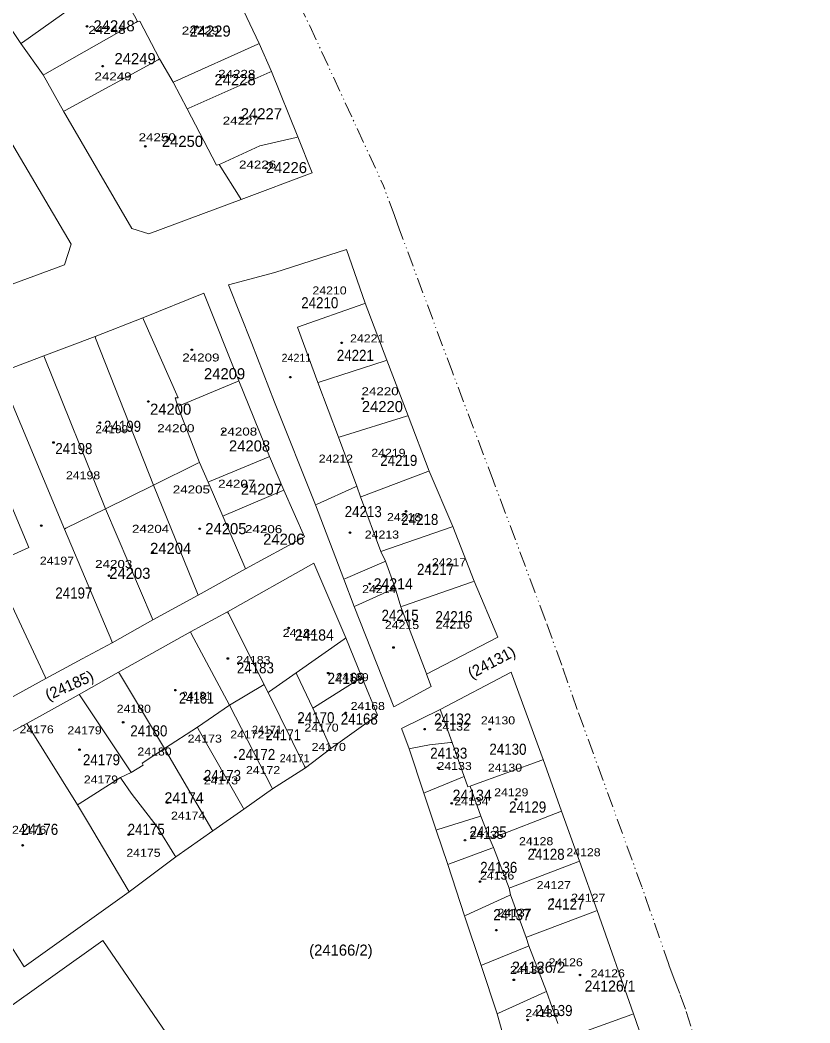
# Model space of a CAD drawing. Extents: x 649608 to 651081, y 237980 to 241202.
# Drawn here: x 650824.6 to 651081.3, y 238660.5 to 238986.3 of the extents above; entities that cross this region are included whole.
import ezdxf

# ---------------------------------------------------------------- set-up
doc = ezdxf.new("R2010")
doc.units = 0
doc.header["$PDMODE"] = 32
doc.header["$PDSIZE"] = 0.5
doc.linetypes.add('DASH_DOUBLE_DOT', pattern=[9.2, 5, -1.2, 0.3, -1.2, 0.3, -1.2])
for name, color, linetype in [('19', 7, 'Continuous'), ('20', 7, 'Continuous'), ('6', 7, 'Continuous')]:
    doc.layers.add(name, color=color, linetype=linetype)
for name, color, linetype, lineweight in [('3', 7, 'Continuous', 13), ('5', 7, 'Continuous', 13), ('52', 7, 'DASH_DOUBLE_DOT', 13)]:
    doc.layers.add(name, color=color, linetype=linetype, lineweight=lineweight)

msp = doc.modelspace()

# ---------------------------------------------------------------- linework, layer by layer
at = {"layer": '3'}
for p, q in [((650919.551, 238936.638), (650896.474, 238928.024)), ((650893.931, 238625.308), (650851.505, 238687.244))]:
    msp.add_line(p, q, dxfattribs=at)
for points in [[(650896.474, 238928.024), (650866.501, 238916.902), (650860.911, 238918.598), (650838.751, 238956.69), (650832.15, 238968.489), (650824.903, 238978.716), (650815.286, 238992.747), (650804.439, 239005.498)], [(650919.551, 238936.638), (650914.867, 238948.335), (650906.317, 238969.569), (650902.354, 238978.677), (650891.135, 239002.272)], [(650820.054, 238949.367), (650841.243, 238913.534), (650838.995, 238906.77), (650799.963, 238892.432), (650770.275, 238881.011), (650758.748, 238876.78), (650749.256, 238873.381), (650736.765, 238868.633), (650722.035, 238862.95)], [(650892.348, 238900.274), (650907.377, 238904.347), (650930.698, 238911.753), (650936.802, 238894.323), (650943.788, 238875.768), (650950.717, 238857.717), (650957.619, 238839.792), (650965.263, 238821.75), (650972.163, 238804.001), (650979.843, 238785.835)], [(650892.348, 238900.274), (650899.901, 238881.247), (650907.252, 238862.117), (650920.617, 238828.809), (650929.839, 238804.682), (650933.238, 238795.794), (650946.119, 238763.137)], [(650895.76, 238869.115), (650884.379, 238897.633), (650864.531, 238889.545), (650848.962, 238883.51), (650832.372, 238877.214), (650817.719, 238871.717), (650805.539, 238866.947), (650792.518, 238861.842), (650760.407, 238849.915)], [(650897.827, 238808.065), (650917.045, 238818.418), (650910.287, 238833.538), (650905.707, 238844.466), (650895.76, 238869.115)], [(650758.169, 238660.693), (650714.231, 238692.51), (650714.379, 238696.621), (650773.885, 238729.057), (650787.528, 238736.436), (650826.802, 238757.704), (650843.776, 238767.23), (650856.602, 238774.451), (650879.964, 238787.538), (650892.055, 238793.996), (650920.073, 238809.821)], [(650920.073, 238809.821), (650930.477, 238785.555), (650935.71, 238772.766)], [(650833.004, 238772.406), (650844.737, 238778.761), (650854.588, 238784.015), (650867.719, 238791.491), (650882.507, 238799.486), (650897.827, 238808.065)], [(650946.119, 238763.137), (650958.223, 238769.746), (650956.746, 238773.738), (650979.843, 238785.835)], [(650791.939, 238782.111), (650803.989, 238756.472), (650833.004, 238772.406)], [(650948.594, 238756.104), (650961.145, 238762.316), (650984.226, 238774.453)], [(650984.226, 238774.453), (650984.338, 238774.16), (650994.654, 238746.036), (651000.56, 238729.25)], [(650935.71, 238772.766), (650940.785, 238760.481), (650925.609, 238749.684), (650917.325, 238743.359), (650906.695, 238736.485), (650897.365, 238729.873), (650887.272, 238722.827), (650875.247, 238714.403), (650860.075, 238703.102)], [(650948.594, 238756.104), (650948.647, 238755.953), (650951.021, 238749.525), (650955.792, 238735.14), (650959.886, 238723.149), (650963.669, 238711.97), (650969.049, 238695.287), (650974.422, 238679.159), (650979.638, 238663.433), (650982.757, 238652.196), (650986.731, 238637.816), (650991.239, 238621.324), (650995.965, 238603.801), (650998.364, 238595.203), (651001.152, 238574.45)], [(651063.379, 238461.895), (651063.305, 238462.395), (651061.473, 238474.842), (651059.17, 238490.663), (651056.406, 238508.519), (651054.341, 238525.331), (651052.076, 238542.318), (651049.059, 238560.151), (651043.67, 238600.336), (651038.659, 238621.53), (651031.567, 238641.552), (651023.953, 238663.427), (651012.132, 238696.964), (651006.434, 238713.032), (651000.56, 238729.25)], [(650860.075, 238703.102), (650825.962, 238678.677), (650821.773, 238685.221)], [(650851.505, 238687.244), (650818.255, 238663.558), (650782.391, 238637.529), (650824.601, 238580.584), (650833.018, 238586.179), (650832.688, 238586.745), (650893.931, 238625.308)]]:
    msp.add_lwpolyline(points, dxfattribs=at)
at = {"layer": '5'}
for points in [[(650824.903, 238978.716), (650825.403, 238979.072), (650854.809, 239000.028), (650861.825, 238987.705), (650862.766, 238985.824)], [(650832.15, 238968.489), (650832.65, 238968.772), (650862.266, 238985.541), (650862.766, 238985.824)], [(650862.766, 238985.824), (650863.556, 238986.011), (650869.959, 238973.705), (650874.391, 238966.117), (650878.962, 238957.522)], [(650874.391, 238966.117), (650874.891, 238966.342), (650901.854, 238978.452), (650902.354, 238978.677)], [(650838.751, 238956.69), (650839.251, 238956.963), (650869.459, 238973.432), (650869.959, 238973.705)], [(650878.962, 238957.522), (650879.462, 238957.742), (650905.817, 238969.349), (650906.317, 238969.569)], [(650878.962, 238957.522), (650888.424, 238939.149), (650889.341, 238939.413)], [(650889.341, 238939.413), (650889.841, 238939.641), (650902.508, 238945.405), (650914.367, 238948.216), (650914.867, 238948.335)], [(650889.341, 238939.413), (650896.161, 238928.524), (650896.474, 238928.024)], [(650914.737, 238886.554), (650936.302, 238894.147), (650936.802, 238894.323)], [(650864.531, 238889.545), (650864.751, 238889.045), (650875.984, 238863.567), (650874.962, 238863.579), (650875.863, 238860.74), (650882.87, 238842.564), (650885.704, 238836.141), (650890.457, 238825.101)], [(650941.848, 238813.662), (650935.229, 238831.363), (650934.09, 238834.906), (650928.106, 238850.774), (650921.359, 238868.55), (650914.737, 238886.554)], [(650848.962, 238883.51), (650849.159, 238883.01), (650867.955, 238835.238)], [(650832.372, 238877.214), (650832.573, 238876.714), (650852.38, 238827.525)], [(650921.359, 238868.55), (650921.859, 238868.711), (650943.288, 238875.607), (650943.788, 238875.768)], [(650817.719, 238871.717), (650817.929, 238871.217), (650839.016, 238820.925)], [(650875.863, 238860.74), (650876.363, 238860.95), (650895.26, 238868.905), (650895.76, 238869.115)], [(650827.458, 238814.978), (650805.75, 238866.447), (650805.539, 238866.947)], [(650928.106, 238850.774), (650928.606, 238850.928), (650950.217, 238857.563), (650950.717, 238857.717)], [(650867.955, 238835.238), (650882.37, 238842.318), (650882.87, 238842.564)], [(650885.704, 238836.141), (650886.204, 238836.349), (650905.207, 238844.258), (650905.707, 238844.466)], [(650935.229, 238831.363), (650935.729, 238831.551), (650957.119, 238839.604), (650957.619, 238839.792)], [(650839.016, 238820.925), (650839.516, 238821.172), (650852.38, 238827.525), (650867.955, 238835.238)], [(650867.955, 238835.238), (650882.303, 238799.986), (650882.507, 238799.486)], [(650890.457, 238825.101), (650890.957, 238825.314), (650909.787, 238833.325), (650910.287, 238833.538)], [(650934.09, 238834.906), (650933.59, 238834.68), (650921.117, 238829.035), (650920.617, 238828.809)], [(650852.38, 238827.525), (650867.506, 238791.991), (650867.719, 238791.491)], [(650890.457, 238825.101), (650897.611, 238808.565), (650897.827, 238808.065)], [(650839.016, 238820.925), (650854.377, 238784.515), (650854.588, 238784.015)], [(650965.263, 238821.75), (650964.763, 238821.577), (650941.848, 238813.662)], [(650816.298, 238809.995), (650816.798, 238810.218), (650827.458, 238814.978)], [(650941.848, 238813.662), (650943.392, 238810.452), (650946.482, 238801.788), (650948.392, 238795.682)], [(650943.392, 238810.452), (650942.892, 238810.239), (650930.339, 238804.895), (650929.839, 238804.682)], [(650972.163, 238804.001), (650971.663, 238803.826), (650948.892, 238795.857), (650948.392, 238795.682)], [(650946.482, 238801.788), (650945.982, 238801.562), (650933.738, 238796.02), (650933.238, 238795.794)], [(650821.271, 238797.545), (650832.771, 238772.906), (650833.004, 238772.406)], [(650903.916, 238770.428), (650892.307, 238793.496), (650892.055, 238793.996)], [(650948.392, 238795.682), (650956.556, 238774.238), (650956.746, 238773.738)], [(650879.964, 238787.538), (650880.231, 238787.038), (650892.673, 238763.728)], [(650914.297, 238774.216), (650929.977, 238785.205), (650930.477, 238785.555)], [(650856.602, 238774.451), (650856.902, 238773.951), (650871.499, 238749.614)], [(650905.198, 238767.795), (650905.698, 238768.148), (650914.297, 238774.216)], [(650914.297, 238774.216), (650914.536, 238773.716), (650919.796, 238762.706)], [(650860.71, 238741.886), (650864.617, 238744.264), (650864.265, 238744.852), (650871.499, 238749.614), (650882.228, 238756.559), (650892.673, 238763.728), (650903.916, 238770.428)], [(650903.916, 238770.428), (650904.159, 238769.928), (650905.198, 238767.795)], [(650919.796, 238762.706), (650920.296, 238763.022), (650935.21, 238772.45), (650935.71, 238772.766)], [(650860.71, 238741.886), (650860.376, 238742.386), (650844.11, 238766.73), (650843.776, 238767.23)], [(650905.198, 238767.795), (650917.077, 238743.859), (650917.325, 238743.359)], [(650892.673, 238763.728), (650906.438, 238736.985), (650906.695, 238736.485)], [(650919.796, 238762.706), (650925.386, 238750.184), (650925.609, 238749.684)], [(650961.145, 238762.316), (650961.327, 238761.816), (650965.051, 238751.593), (650968.909, 238740.542)], [(650843.322, 238731.299), (650827.115, 238757.204), (650826.802, 238757.704)], [(650897.365, 238729.873), (650897.081, 238730.373), (650882.512, 238756.059), (650882.228, 238756.559)], [(650951.021, 238749.525), (650951.521, 238749.626), (650957.675, 238750.87), (650964.551, 238751.544), (650965.051, 238751.593)], [(650871.499, 238749.614), (650886.978, 238723.327), (650887.272, 238722.827)], [(650970.888, 238737.388), (650971.388, 238737.57), (650994.154, 238745.854), (650994.654, 238746.036)], [(650843.322, 238731.299), (650843.822, 238731.618), (650857.248, 238740.177), (650860.71, 238741.886)], [(650857.248, 238740.177), (650857.595, 238739.677), (650860.756, 238735.125), (650869.187, 238724.182), (650874.937, 238714.903), (650875.247, 238714.403)], [(650955.792, 238735.14), (650956.292, 238735.346), (650968.409, 238740.336), (650968.909, 238740.542)], [(650968.909, 238740.542), (650970.097, 238737.227), (650970.888, 238737.388), (650974.373, 238727.694), (650977.245, 238720.162), (650978.452, 238717.453), (650983.561, 238704.298), (650984.021, 238702.059), (650989.061, 238688.248), (650989.987, 238685.484), (650995.652, 238670.697), (650999.401, 238660.225)], [(650860.075, 238703.102), (650859.779, 238703.602), (650846.865, 238725.39), (650843.322, 238731.299)], [(650959.886, 238723.149), (650960.386, 238723.306), (650973.873, 238727.537), (650974.373, 238727.694)], [(650977.245, 238720.162), (650977.745, 238720.357), (651000.56, 238729.25)], [(650963.669, 238711.97), (650964.169, 238712.155), (650977.952, 238717.268), (650978.452, 238717.453)], [(650983.561, 238704.298), (650984.061, 238704.489), (651005.934, 238712.841), (651006.434, 238713.032)], [(650969.049, 238695.287), (650969.549, 238695.513), (650983.521, 238701.833), (650984.021, 238702.059)], [(650989.061, 238688.248), (650989.561, 238688.437), (651011.632, 238696.775), (651012.132, 238696.964)], [(650974.422, 238679.159), (650974.922, 238679.362), (650989.487, 238685.281), (650989.987, 238685.484)], [(650979.638, 238663.433), (650980.138, 238663.66), (650995.152, 238670.47), (650995.652, 238670.697)], [(651000.938, 238655.114), (651023.453, 238663.246), (651023.953, 238663.427)]]:
    msp.add_lwpolyline(points, dxfattribs=at)
at = {"layer": '52'}
for points in [[(650586.911, 239277.281), (650736.548, 239179.048), (650838.83, 239107.702), (650862.891, 239089.627), (650874.137, 239074.489), (650882.719, 239057.758), (650918.743, 238984.453), (650942.749, 238932.427)], [(651081.326, 238461.798), (651080.759, 238465.959), (651079.219, 238474.548), (651060.64, 238594.17), (651059.155, 238604.083), (651058.44, 238609.613), (651056.636, 238614.788), (651055.058, 238619.632), (651053.581, 238624.323), (651040.863, 238664.96), (651038.983, 238669.983), (651037.177, 238674.674), (651035.497, 238679.416), (651026.689, 238704.697), (651005.715, 238762.299), (651000.638, 238776.753), (650995.266, 238791.57), (650978.475, 238836.494), (650965.122, 238871.866), (650947.956, 238918.149), (650946.31, 238922.796), (650942.749, 238932.427)]]:
    msp.add_lwpolyline(points, dxfattribs=at)
at = {"layer": '6'}
for p in [(650846.34, 238984.258), (650882.116, 238984.194), (650851.422, 238971.35), (650890.891, 238968.099), (650896.516, 238954.359), (650865.315, 238945.303), (650904.524, 238938.179), (650929.137, 238881.436), (650880.419, 238879.186), (650912.419, 238870.281), (650866.305, 238862.391), (650935.974, 238863.271), (650850.542, 238855.517), (650890.702, 238852.628), (650835.46, 238849.069), (650943.124, 238844.54), (650898.027, 238834.783), (650950.058, 238826.727), (650831.505, 238822.061), (650882.98, 238821.025), (650904.149, 238820.801), (650931.809, 238819.794), (650867.633, 238813.364), (650853.525, 238805.77), (650957.171, 238808.716), (650938.221, 238803.123), (650911.874, 238788.808), (650964.773, 238788.869), (650945.961, 238782.462), (650892.133, 238778.862), (650924.745, 238774.13), (650875.106, 238768.576), (650930.467, 238761.225), (650858.1, 238758.168), (650915.607, 238758.787), (650905.137, 238753.456), (650956.067, 238755.92), (650977.281, 238755.84), (650843.931, 238749.264), (650894.575, 238746.8), (650960.493, 238743.366), (650884.568, 238739.693), (650872.512, 238732.008), (650964.899, 238731.845), (650985.818, 238733.099), (650859.926, 238721.639), (650825.443, 238718.19), (650969.2, 238719.832), (650991.897, 238716.774), (650974.116, 238706.37), (650997.684, 238700.64), (650979.403, 238690.609), (651006.557, 238676.039), (650985.096, 238674.458), (650989.577, 238661.446)]:
    msp.add_point(p, dxfattribs=at)

# ---------------------------------------------------------------- texts
at = {"layer": '19'}
for s, p in [('24248', (650848.463, 238982.655)), ('24229', (650879.671, 238980.949)), ('24249', (650855.303, 238971.99)), ('24228', (650887.793, 238965.165)), ('24227', (650896.344, 238954.073)), ('24250', (650870.693, 238945.113)), ('24226', (650904.467, 238936.582)), ('24209', (650884.373, 238869.603)), ('24200', (650866.846, 238858.086)), ('24220', (650935.675, 238858.939)), ('24208', (650892.496, 238846.14)), ('24207', (650896.343, 238832.062)), ('24205', (650884.801, 238819.263)), ('24206', (650903.611, 238815.85)), ('24204', (650866.845, 238812.864)), ('24203', (650853.592, 238804.759)), ('(24166/2)', (650918.574, 238682.323)), ('24126/2', (650984.412, 238676.776))]:
    msp.add_text(s, height=3.6, dxfattribs=at).set_placement(p)
for s, width, p in [('24210', 0.9, (650915.992, 238892.667)), ('24221', 0.9, (650927.553, 238875.576)), ('24199', 0.9, (650851.883, 238852.54)), ('24198', 0.9, (650836.064, 238845.288)), ('24219', 0.9, (650941.661, 238841.448)), ('24213', 0.9, (650930.117, 238824.81)), ('24218', 0.9, (650948.5, 238822.25)), ('24217', 0.9, (650953.631, 238806.039)), ('24214', 0.95, (650939.522, 238801.346)), ('24197', 0.9, (650836.065, 238798.36)), ('24215', 0.9, (650942.087, 238791.108)), ('24216', 0.9, (650959.616, 238790.681)), ('24184', 0.95, (650913.871, 238784.709)), ('24183', 0.9, (650895.061, 238774.044)), ('24169', 0.9, (650924.56, 238770.631)), ('24181', 0.85, (650876.251, 238764.231)), ('24170', 0.9, (650914.726, 238757.832)), ('24168', 0.9, (650928.834, 238757.406)), ('24132', 0.9, (650959.188, 238757.406)), ('24180', 0.9, (650860.433, 238753.566)), ('24171', 0.85, (650904.467, 238752.286)), ('24130', 0.9, (650977.143, 238747.594)), ('24179', 0.9, (650845.044, 238744.181)), ('24172', 0.9, (650895.489, 238745.887)), ('24133', 0.9, (650957.906, 238746.314)), ('24173', 0.9, (650884.374, 238739.061)), ('24174', 0.95, (650871.547, 238731.809)), ('24134', 0.95, (650965.173, 238732.662)), ('24129', 0.9, (650983.556, 238728.823)), ('24176', 0.9, (650824.951, 238721.57)), ('24175', 0.9, (650859.578, 238721.57)), ('24135', 0.9, (650970.731, 238720.717)), ('24128', 0.9, (650989.54, 238713.465)), ('24136', 0.9, (650974.152, 238709.199)), ('24127', 0.9, (650995.954, 238697.254)), ('24137', 0.9, (650978.427, 238693.841)), ('24126/1', 0.95, (651008.085, 238670.64)), ('24139', 0.9, (650992.108, 238662.698))]:
    msp.add_text(s, height=3.6, dxfattribs=dict(at, width=width)).set_placement(p)
for s, rotation, p in [('(24131)', 27.737, (650971.334, 238772.194)), ('(24185)', 23.999, (650833.78, 238765.132))]:
    msp.add_text(s, height=3.6, rotation=rotation, dxfattribs=at).set_placement(p)
at = {"layer": '20'}
for s, width, p in [('24248', 1.25, (650846.807, 238981.844)), ('24229', 1.25, (650877.167, 238981.609)), ('24249', 1.25, (650848.782, 238966.719)), ('24228', 1.25, (650889, 238967.537)), ('24227', 1.25, (650890.473, 238952.343)), ('24250', 1.25, (650863.135, 238946.937)), ('24226', 1.25, (650895.76, 238938.066)), ('24210', 1.15, (650919.631, 238897.175)), ('24221', 1.15, (650931.874, 238881.585)), ('24209', 1.25, (650877.334, 238875.377)), ('24220', 1.25, (650935.579, 238864.409)), ('24199', 1.1, (650849.066, 238852.074)), ('24200', 1.25, (650869.191, 238852.399)), ('24208', 1.25, (650889.58, 238851.317)), ('24212', 1.15, (650921.696, 238842.533)), ('24219', 1.15, (650938.768, 238844.415)), ('24198', 1.15, (650839.519, 238837.102)), ('24205', 1.25, (650874.243, 238832.505)), ('24207', 1.25, (650888.976, 238834.364)), ('24218', 1.15, (650943.871, 238823.517)), ('24204', 1.25, (650860.984, 238819.711)), ('24206', 1.25, (650897.722, 238819.601)), ('24213', 1.15, (650936.658, 238817.85)), ('24197', 1.15, (650831.044, 238809.361)), ('24203', 1.25, (650849, 238808.274)), ('24217', 1.15, (650958.462, 238808.85)), ('24214', 1.15, (650935.784, 238800.129)), ('24215', 1.15, (650943.178, 238788.446)), ('24216', 1.15, (650959.679, 238788.61)), ('24184', 1.15, (650909.972, 238785.894)), ('24183', 1.15, (650894.868, 238777.084)), ('24169', 1.1, (650927.264, 238771.507)), ('24180', 1.15, (650856.018, 238761.249)), ('24168', 1.15, (650932.057, 238762.14)), ('24130', 1.15, (650974.379, 238757.473)), ('24176', 1.15, (650824.435, 238754.558)), ('24179', 1.15, (650840.007, 238754.223)), ('24170', 1.15, (650917.026, 238755.114)), ('24132', 1.15, (650959.687, 238755.466)), ('24173', 1.15, (650879.076, 238751.546)), ('24172', 1.15, (650892.914, 238752.884)), ('24170', 1.15, (650919.366, 238748.839)), ('24180', 1.15, (650862.747, 238747.349)), ('24172', 1.15, (650898.025, 238741.324)), ('24133', 1.15, (650960.288, 238742.644)), ('24130', 1.15, (650976.656, 238742.115)), ('24179', 1.15, (650845.337, 238738.266)), ('24173', 1.15, (650884.332, 238737.965)), ('24129', 1.15, (650978.702, 238734.105)), ('24134', 1.15, (650965.729, 238731.219)), ('24174', 1.15, (650873.67, 238726.53)), ('24176', 1.15, (650821.991, 238721.907)), ('24135', 1.15, (650970.642, 238720.253)), ('24128', 1.15, (650986.78, 238718.214)), ('24175', 1.15, (650859.149, 238714.441)), ('24128', 1.15, (651002.168, 238714.618)), ('24136', 1.15, (650974.097, 238707.055)), ('24127', 1.15, (650992.527, 238703.953)), ('24127', 1.15, (651003.719, 238699.848)), ('24137', 1.15, (650979.734, 238694.979)), ('24138', 1.15, (650983.826, 238676.397)), ('24126', 1.15, (650996.385, 238678.87)), ('24126', 1.15, (651010.04, 238675.282)), ('24139', 1.15, (650988.817, 238662.345))]:
    msp.add_text(s, height=2.6, dxfattribs=dict(at, width=width)).set_placement(p)
for s, p in [('24211', (650909.587, 238875.289)), ('24181', (650877.136, 238765.486)), ('24171', (650900.022, 238754.445)), ('24171', (650909.006, 238745.18))]:
    msp.add_text(s, height=2.6, dxfattribs=at).set_placement(p)

doc.saveas('drawing.dxf')
